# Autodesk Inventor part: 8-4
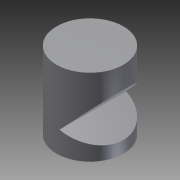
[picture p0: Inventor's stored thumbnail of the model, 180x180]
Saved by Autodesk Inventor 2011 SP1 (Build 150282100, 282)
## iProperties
Created: 2014-01
Part Number: 8-4
Document SubType Name: Modeling
Designer: Administrator
Density: 1 g/cm^3
Author: Administrator
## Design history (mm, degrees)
sketch "草图1"
  geometry: C1 r 13 at (0, 0); 1 further point
  constraints: 1 centre point, 1 coincident
  dimensions: "d0" = 26 diameter of C1
extrude "拉伸1" new body sketch "草图1" distance "d1" = 30; taper "d2" = 0 deg
sketch "草图2"
  geometry: L1 (13, 0)-(13, 30) reference; L2 (-13, 0)-(-13, 30) reference; L3 (-13, 30)-(13, 30) reference; L4 (-13, 0)-(13, 0) reference; L5 (-13, 4.591)-(-1.085, 8.636); L6 (-1.085, 8.636)-(-13, 21.561); 1 further point
  constraints: 4 end point, 2 point on line
extrude "拉伸2" cut sketch "草图2" stored distance "d3" = 30; taper "d4" = 0 deg
node "实体1"
